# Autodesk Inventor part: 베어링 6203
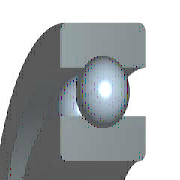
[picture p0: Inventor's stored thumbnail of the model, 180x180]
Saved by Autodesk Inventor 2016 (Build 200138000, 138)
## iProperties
IsCustomPart: 0
Created: 2009-02
Part Number: 베어링 6203
Material: 강철, 연강
Description: 깊은 그루브 볼 베어링
Document SubType Name: Modeling
Standard: KS B 2023
Standards Organization: KS
Language: ko-KR
Size Designation: 6203 - 17 x 40 x 12
Categories: <MemberInstance><Categories><Category DisplayName="샤프트 부품" InternalName="7f7aeb1f-a693-4053-b835-cee3144e0d98" Mnemonic="SHFT"><Category DisplayName="베어링" Inter
Density: 1 g/cm^3
Appearance: 밝은 황색
Author: pww
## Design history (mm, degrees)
sketch "스케치" dims "d0" = 5.98 (= -0.26 x WD + 0.26 x BD)
  geometry: L1 (3.01, 14.25)-(8.99, 14.25); L2 (6, 14.25)-(6, 11.26); L3 (6, 14.25)-(6, 17.24); L4 (3.778, 12.249)-(0, 12.249); L5 (0, 8.5)-(12, 8.5); L6 (3.778, 16.251)-(0, 16.251); L7 (0, 20)-(12, 20); L8 (12, 8.5)-(12, 12.249); L9 (8.222, 12.249)-(12, 12.249); L10 (8.222, 16.251)-(12, 16.251); L11 (12, 20)-(12, 16.251); L12 (-1.4, 0)-(8.4, 0) reference; L13 (0, -0.3)-(0, 5.3) reference
  constraints: 22 end point, 4 point on line, 2 collinear, 2 perpendicular, 2 symmetric about line, 1 midpoint, 1 parallel, 14 other
  dimensions: "d9" = 17 diameter of L5 L12 (= WD); "d11" = 40 diameter of L7 L12 (= BD); "d12" = 12 distance between parallel lines of L8 L13 (= KB); "d13" = 24.498 diameter of L9 L12 (= 0.326 x BD + 0.674 x WD)
revolve "본체" stored, may be unused: angle "d6" = 90 deg
revolve "볼" stored, may be unused: angle "d7" = 90 deg
pattern_circular "IDS_ARRAYBALL[SIMPL:T]" dims angle "d3" = 360 deg
body "Solid1"
fillet "모깎기1" dims "d1" = 0.6 (= KRS)
other parameters: "WD" = 17 [user parameter; used in 5 equation terms], "BD" = 40 [user parameter; used in 5 equation terms], "KB" = 12 [user parameter; used in 1 equation term], "KRS" = 0.6 [user parameter; used in 1 equation term], "d4" = 0, "d5" = 0, "d8" = 0, "d14" = 0, "d15" = 0, "BBA" = 0 [user parameter], "BC0" = 4750000 [user parameter], "BC" = 9560000 [user parameter], "WR" = 8.5 (= 0.5 x WD) [user parameter]
